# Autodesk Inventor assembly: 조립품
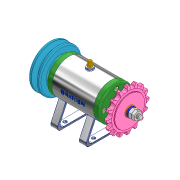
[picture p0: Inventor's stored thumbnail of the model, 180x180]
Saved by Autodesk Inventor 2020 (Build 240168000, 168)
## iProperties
Created: 2021-12
Part Number: 조립품
Document SubType Name: Assembly
Designer: MIRAE
Author: MIRAE
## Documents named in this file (16)
- C:\Users\MIRAE\Desktop\711206V1027\조립품.iam
- C:\Users\MIRAE\Desktop\711206V1027\본체.ipt
- C:\Users\MIRAE\Desktop\711206V1027\베어링 6002.ipt
- C:\Users\MIRAE\Desktop\711206V1027\오일 실 15 x 25 x 7.ipt
- C:\Users\MIRAE\Desktop\711206V1027\커버.ipt
- C:\Users\MIRAE\Desktop\711206V1027\V벨트풀리.ipt
- C:\Users\MIRAE\Desktop\711206V1027\너트 M8.ipt
- C:\Users\MIRAE\Desktop\711206V1027\스프로킷.ipt
- C:\Users\MIRAE\Desktop\711206V1027\스프링와셔 8.ipt
- C:\Users\MIRAE\Desktop\711206V1027\와셔 8 x 17.ipt
- C:\Users\MIRAE\Desktop\711206V1027\키 3 x 3.ipt
- C:\Users\MIRAE\Desktop\711206V1027\축.ipt
- C:\Users\MIRAE\Desktop\711206V1027\볼트 M4 x 12.ipt
- C:\Users\MIRAE\Desktop\711206V1027\니플 M6 x 0.75.ipt
- C:\Users\MIRAE\Desktop\711206V1027\볼트 M6 x 8.ipt
- C:\Users\MIRAE\Desktop\711206V1027\와셔 6 x 11.5.ipt
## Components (11 placed, 3 different names)
1. KS B 2023 6002 - 15 x 32 x 9:1
2. KS B 2023 6002 - 15 x 32 x 9:2
3. V벨트풀리:1 — 각도:4
4. ISO 4762 M4 x 12:2
5. ISO 4762 M4 x 12:3
6. ISO 4762 M4 x 12:4
7. ISO 4762 M4 x 12:5
8. ISO 4762 M4 x 12:1
9. ISO 4762 M4 x 12:6
10. ISO 4762 M4 x 12:7
11. ISO 4762 M4 x 12:8
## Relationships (1: Angle 1)
- 각도:4 [Angle]: V벨트풀리:1
